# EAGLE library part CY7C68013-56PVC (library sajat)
Cypress EZ-USB FX2
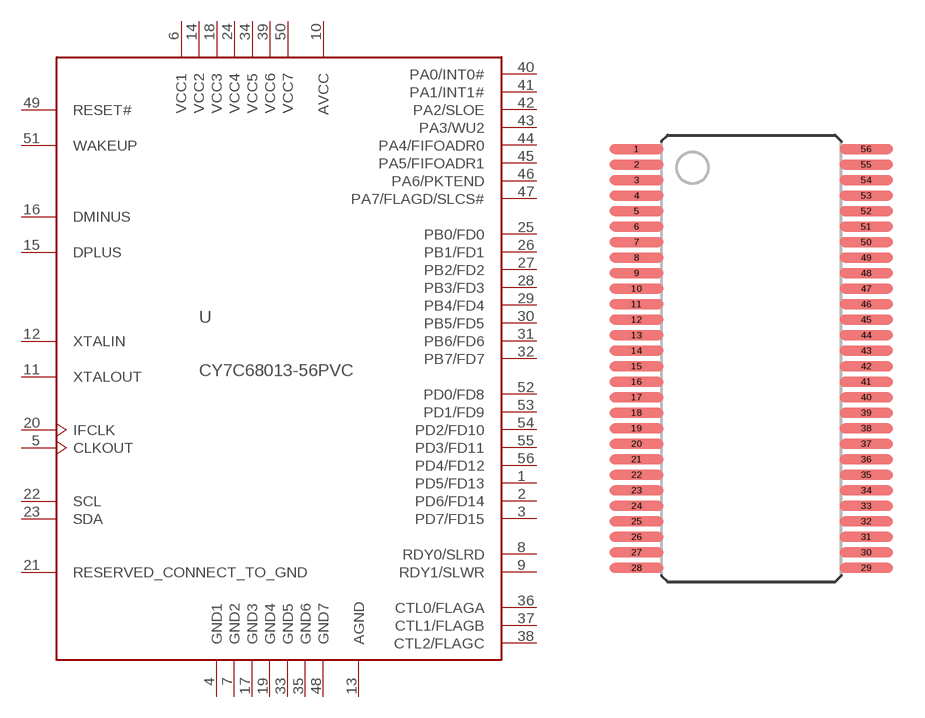
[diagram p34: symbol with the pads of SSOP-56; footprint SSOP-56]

Designator prefix U

## CY7C68013-56PVC  [SSOP-56]
1  PD5/FD13
2  PD6/FD14
3  PD7/FD15
4  GND1
5  CLKOUT  out
6  VCC1
7  GND2
8  RDY0/SLRD
9  RDY1/SLWR
10  AVCC
11  XTALOUT
12  XTALIN
13  AGND
14  VCC2
15  DPLUS
16  DMINUS
17  GND3
18  VCC3
19  GND4
20  IFCLK
21  RESERVED_CONNECT_TO_GND  in
22  SCL
23  SDA
24  VCC4
25  PB0/FD0
26  PB1/FD1
27  PB2/FD2
28  PB3/FD3
29  PB4/FD4
30  PB5/FD5
31  PB6/FD6
32  PB7/FD7
33  GND5
34  VCC5
35  GND6
36  CTL0/FLAGA
37  CTL1/FLAGB
38  CTL2/FLAGC
39  VCC6
40  PA0/INT0#
41  PA1/INT1#
42  PA2/SLOE
43  PA3/WU2
44  PA4/FIFOADR0
45  PA5/FIFOADR1
46  PA6/PKTEND
47  PA7/FLAGD/SLCS#
48  GND7
49  RESET#  in
50  VCC7
51  WAKEUP
52  PD0/FD8
53  PD1/FD9
54  PD2/FD10
55  PD3/FD11
56  PD4/FD12

## Footprint SSOP-56 (pad centres in mm)
56-lead Shrunk Small Outline Package SSOP56
smd 2.2 x 0.4: 1 -4.7,8.572; 2 -4.7,7.938; 3 -4.7,7.303; 4 -4.7,6.668; 5 -4.7,6.032; 6 -4.7,5.397; 7 -4.7,4.763; 8 -4.7,4.128; 9 -4.7,3.493; 10 -4.7,2.857; 11 -4.7,2.223; 12 -4.7,1.587; 13 -4.7,0.953; 14 -4.7,0.318; 15 -4.7,-0.318; 16 -4.7,-0.953; 17 -4.7,-1.587; 18 -4.7,-2.223; 19 -4.7,-2.857; 20 -4.7,-3.493; 21 -4.7,-4.128; 22 -4.7,-4.763; 23 -4.7,-5.397; 24 -4.7,-6.032; 25 -4.7,-6.668; 26 -4.7,-7.303; 27 -4.7,-7.938; 28 -4.7,-8.572; 29 4.7,-8.572; 30 4.7,-7.938; 31 4.7,-7.303; 32 4.7,-6.668; 33 4.7,-6.032; 34 4.7,-5.397; 35 4.7,-4.763; 36 4.7,-4.128; 37 4.7,-3.493; 38 4.7,-2.857; 39 4.7,-2.223; 40 4.7,-1.587; 41 4.7,-0.953; 42 4.7,-0.318; 43 4.7,0.318; 44 4.7,0.953; 45 4.7,1.587; 46 4.7,2.223; 47 4.7,2.857; 48 4.7,3.493; 49 4.7,4.128; 50 4.7,4.763; 51 4.7,5.397; 52 4.7,6.032; 53 4.7,6.668; 54 4.7,7.303; 55 4.7,7.938; 56 4.7,8.572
